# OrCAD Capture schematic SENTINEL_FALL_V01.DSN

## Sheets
1 PG1_BLOCK_DIAGRAM: title: SENTINEL_FALL; rev: V01; note: V01
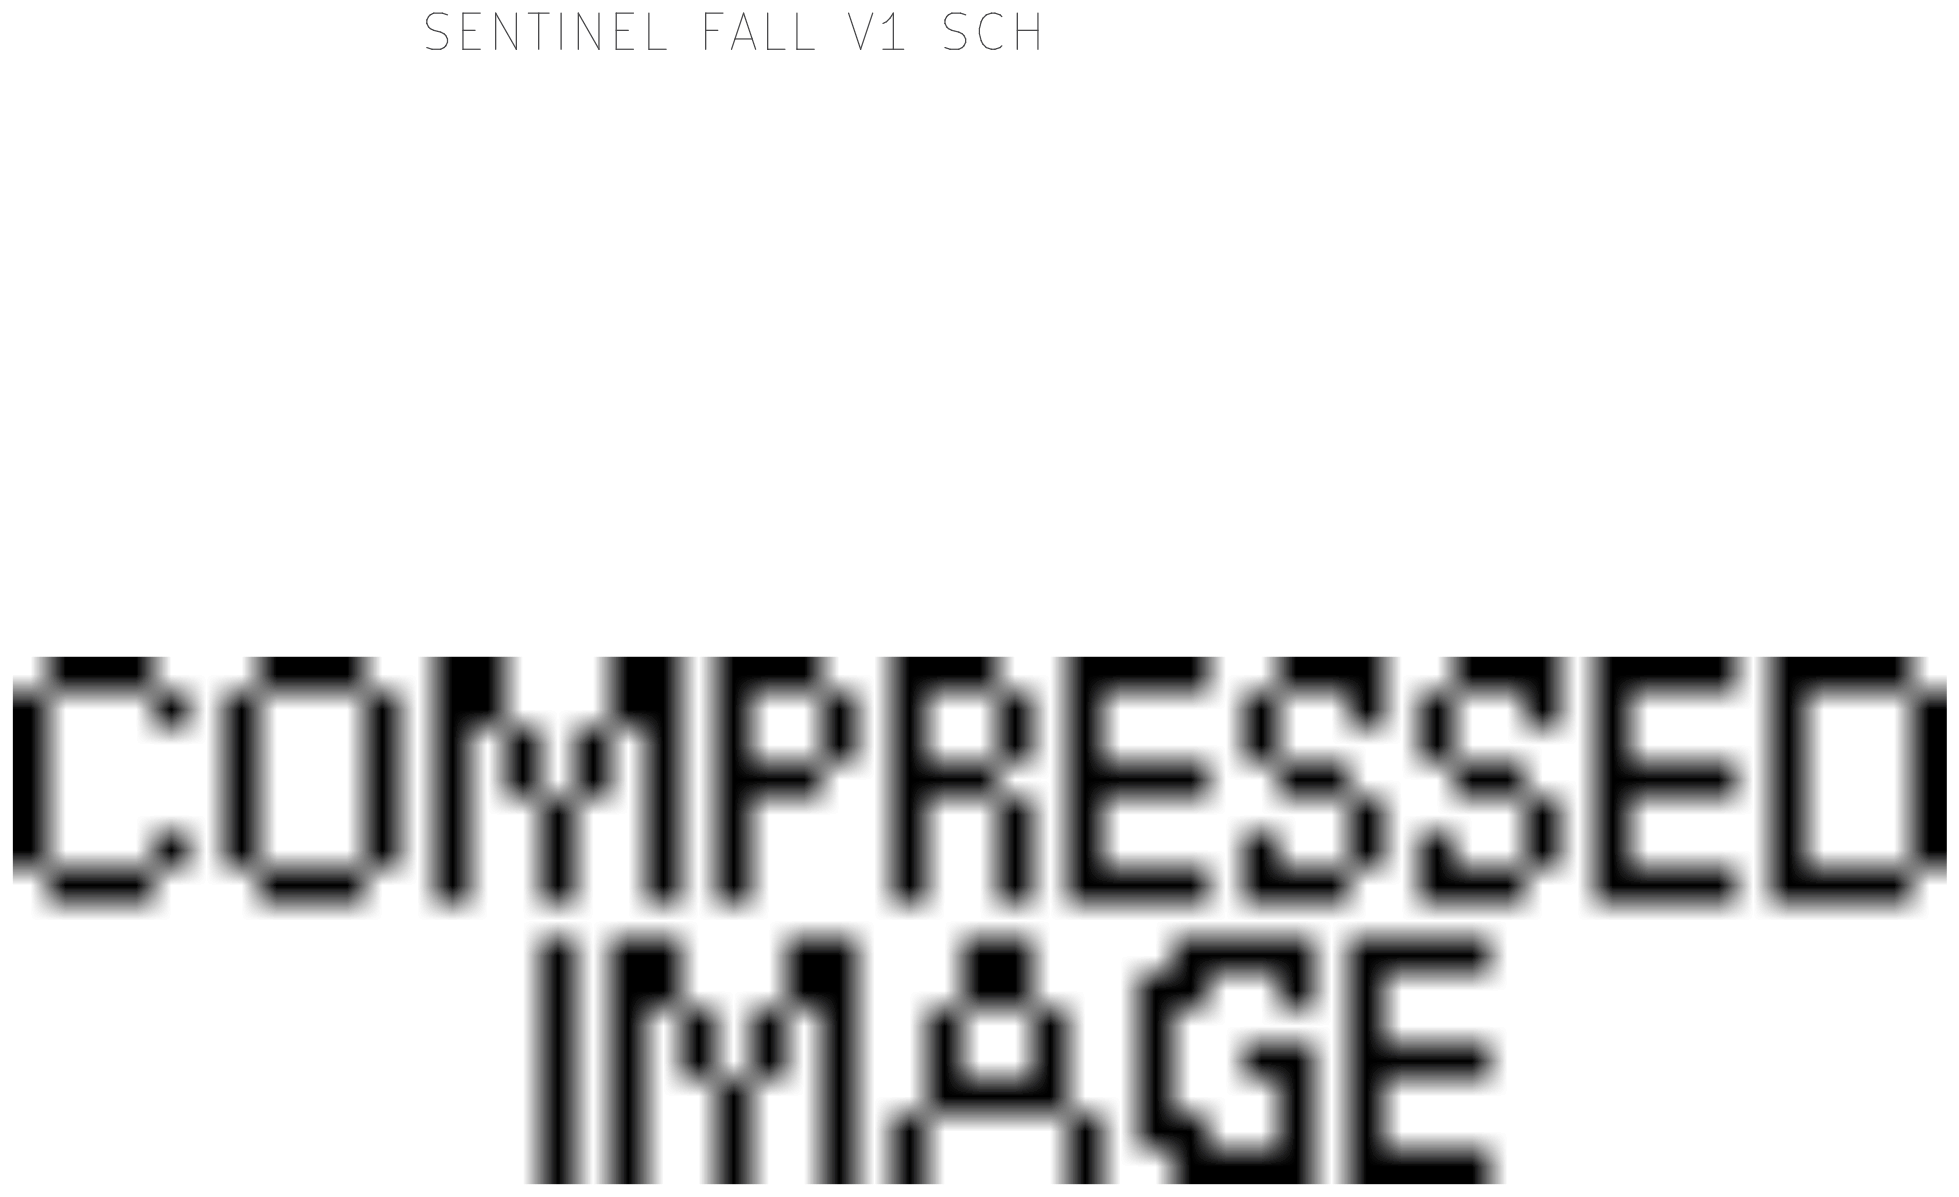
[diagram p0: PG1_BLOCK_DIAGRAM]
2 PG2_BATTERY_CHARGER: size A3
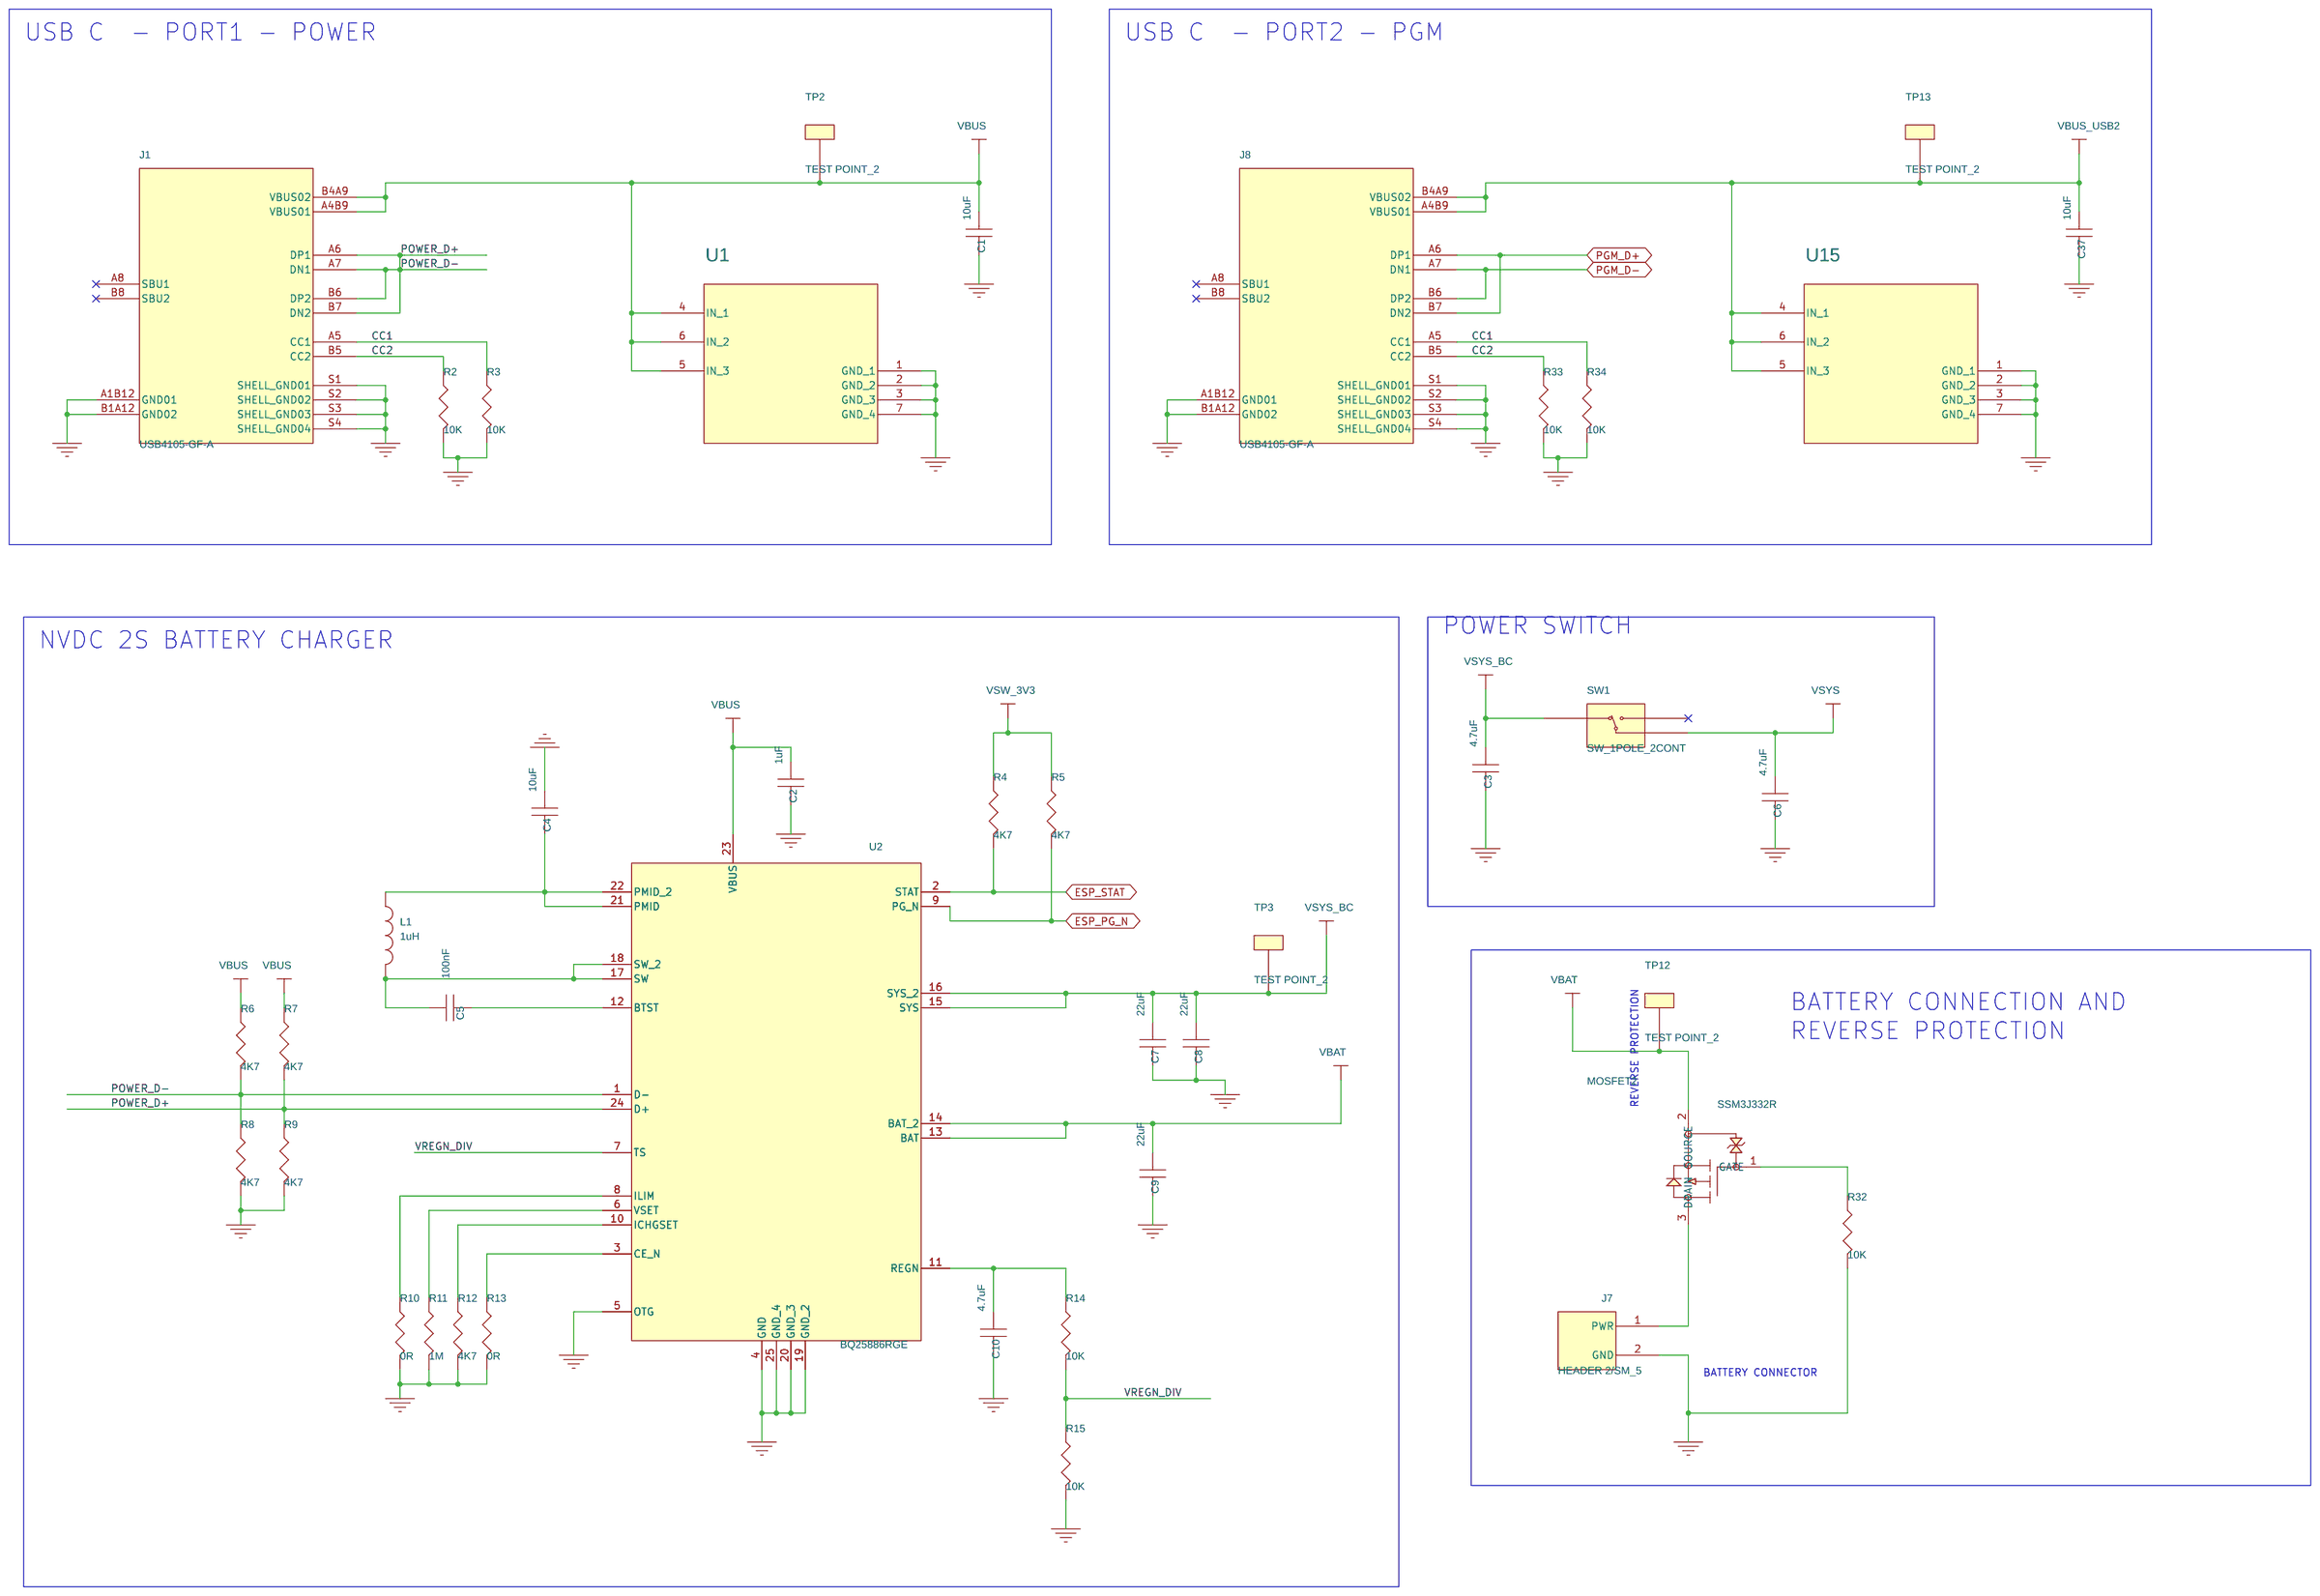
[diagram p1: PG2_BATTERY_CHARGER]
3 PG3_POWER_REG: size A4
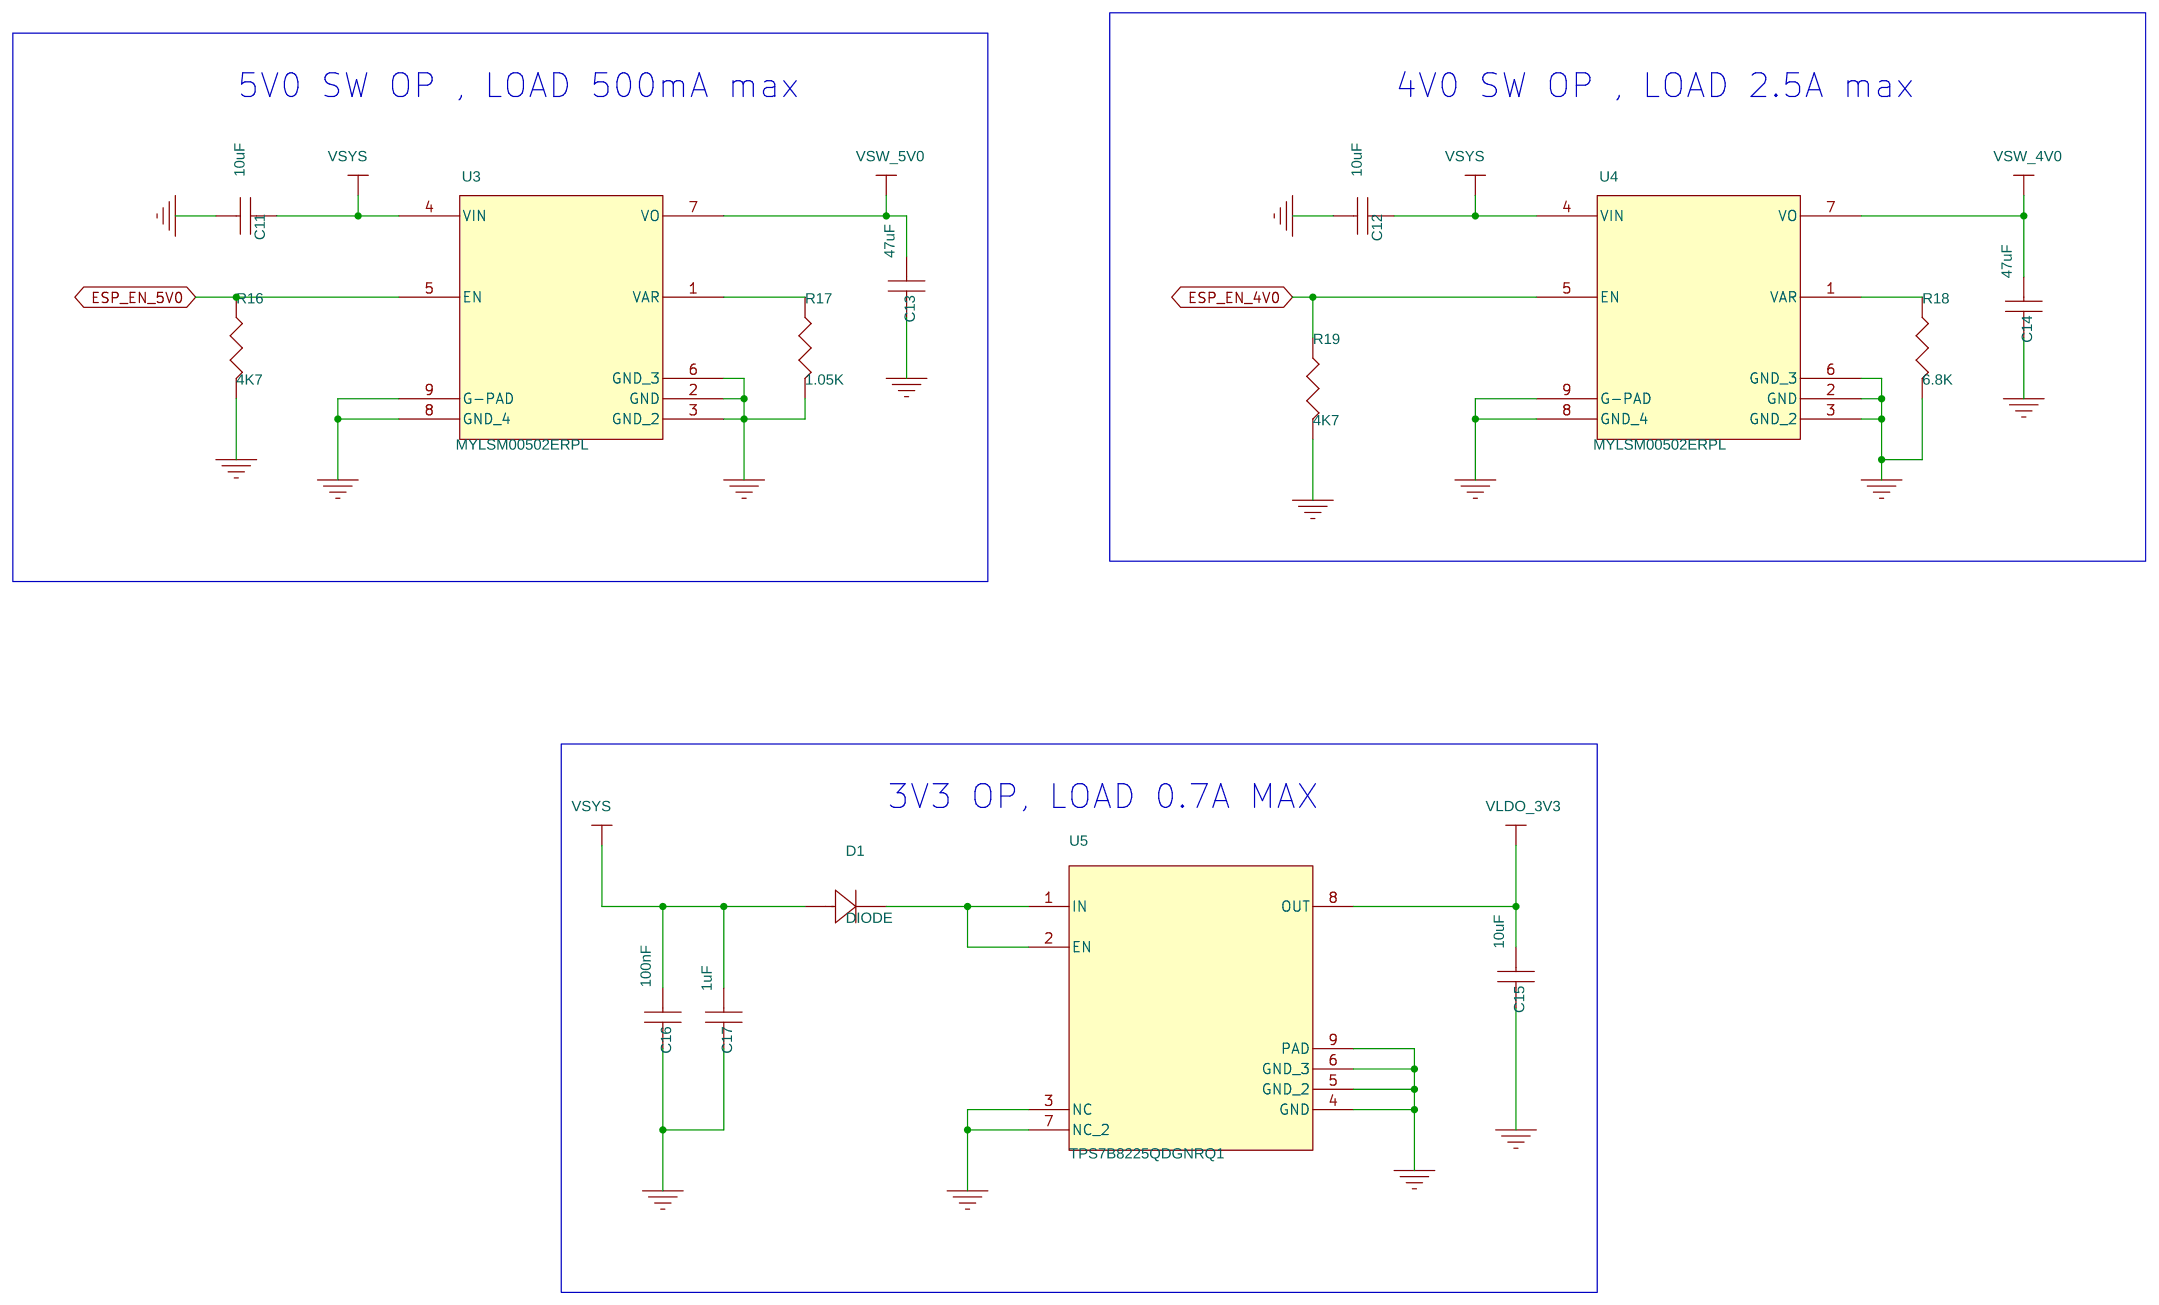
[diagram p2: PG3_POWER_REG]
4 PG4_ESP32: size A3
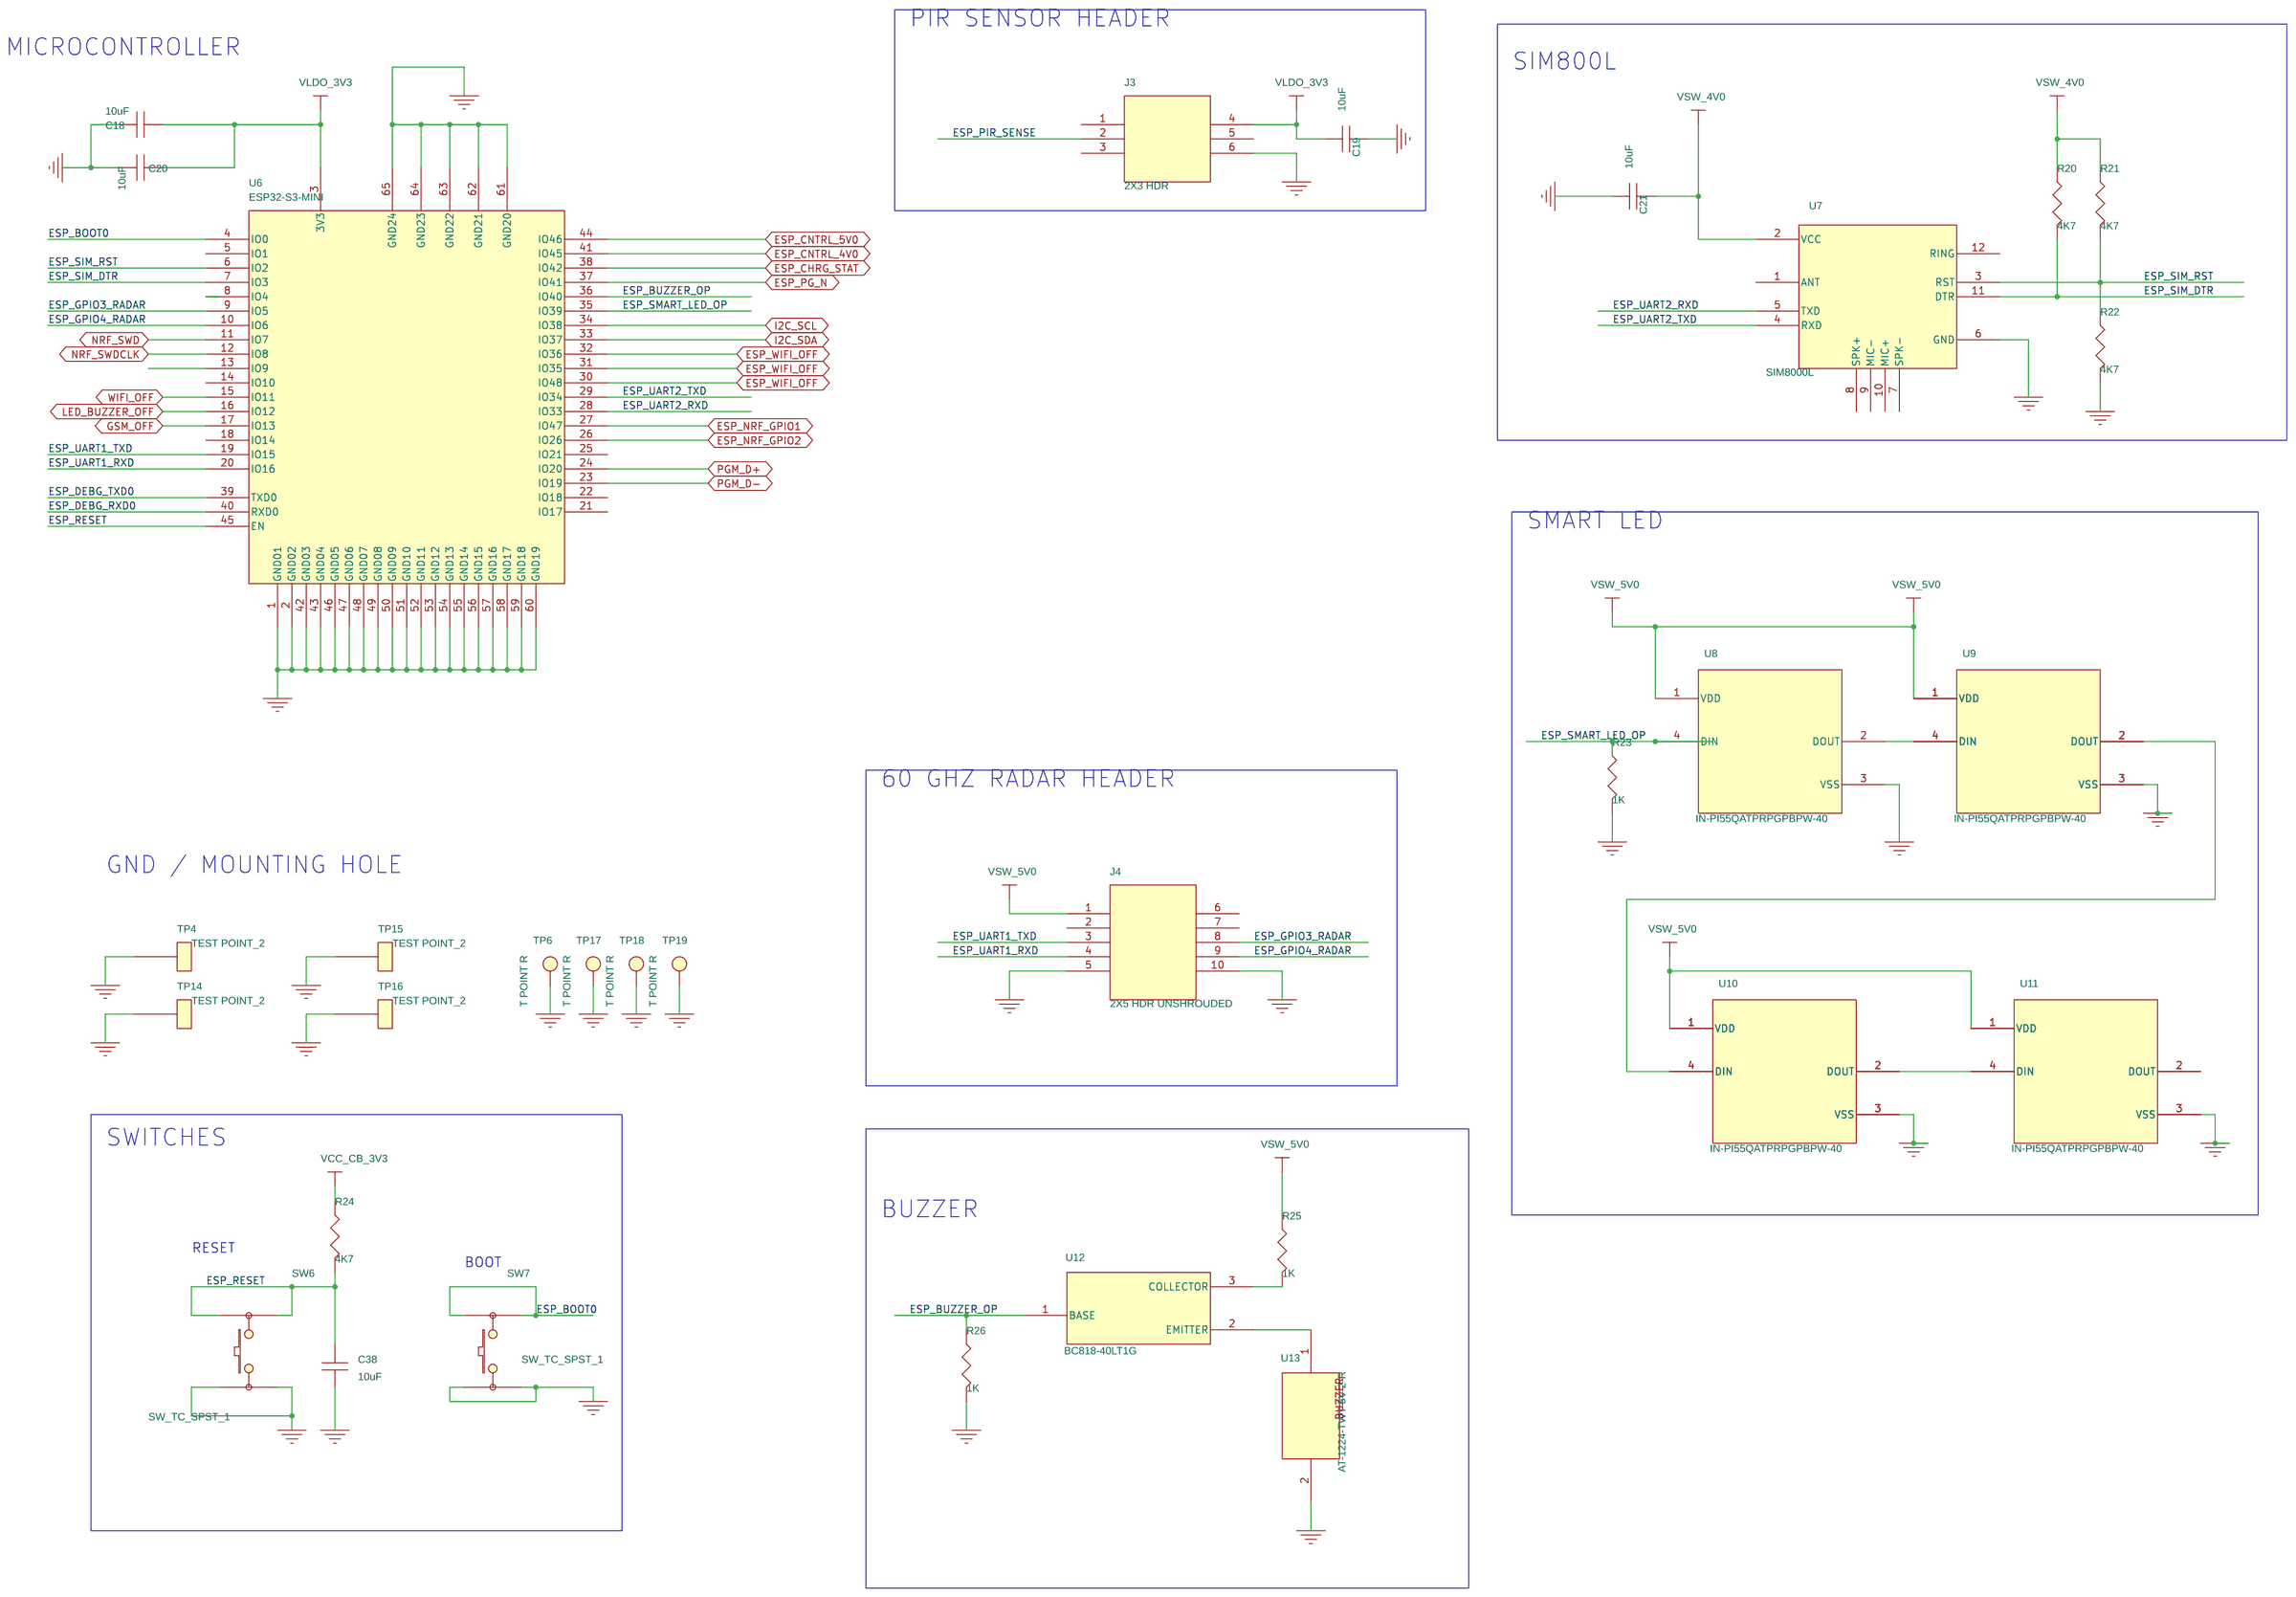
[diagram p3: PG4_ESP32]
5 PG5_NRF_SOC: size A3
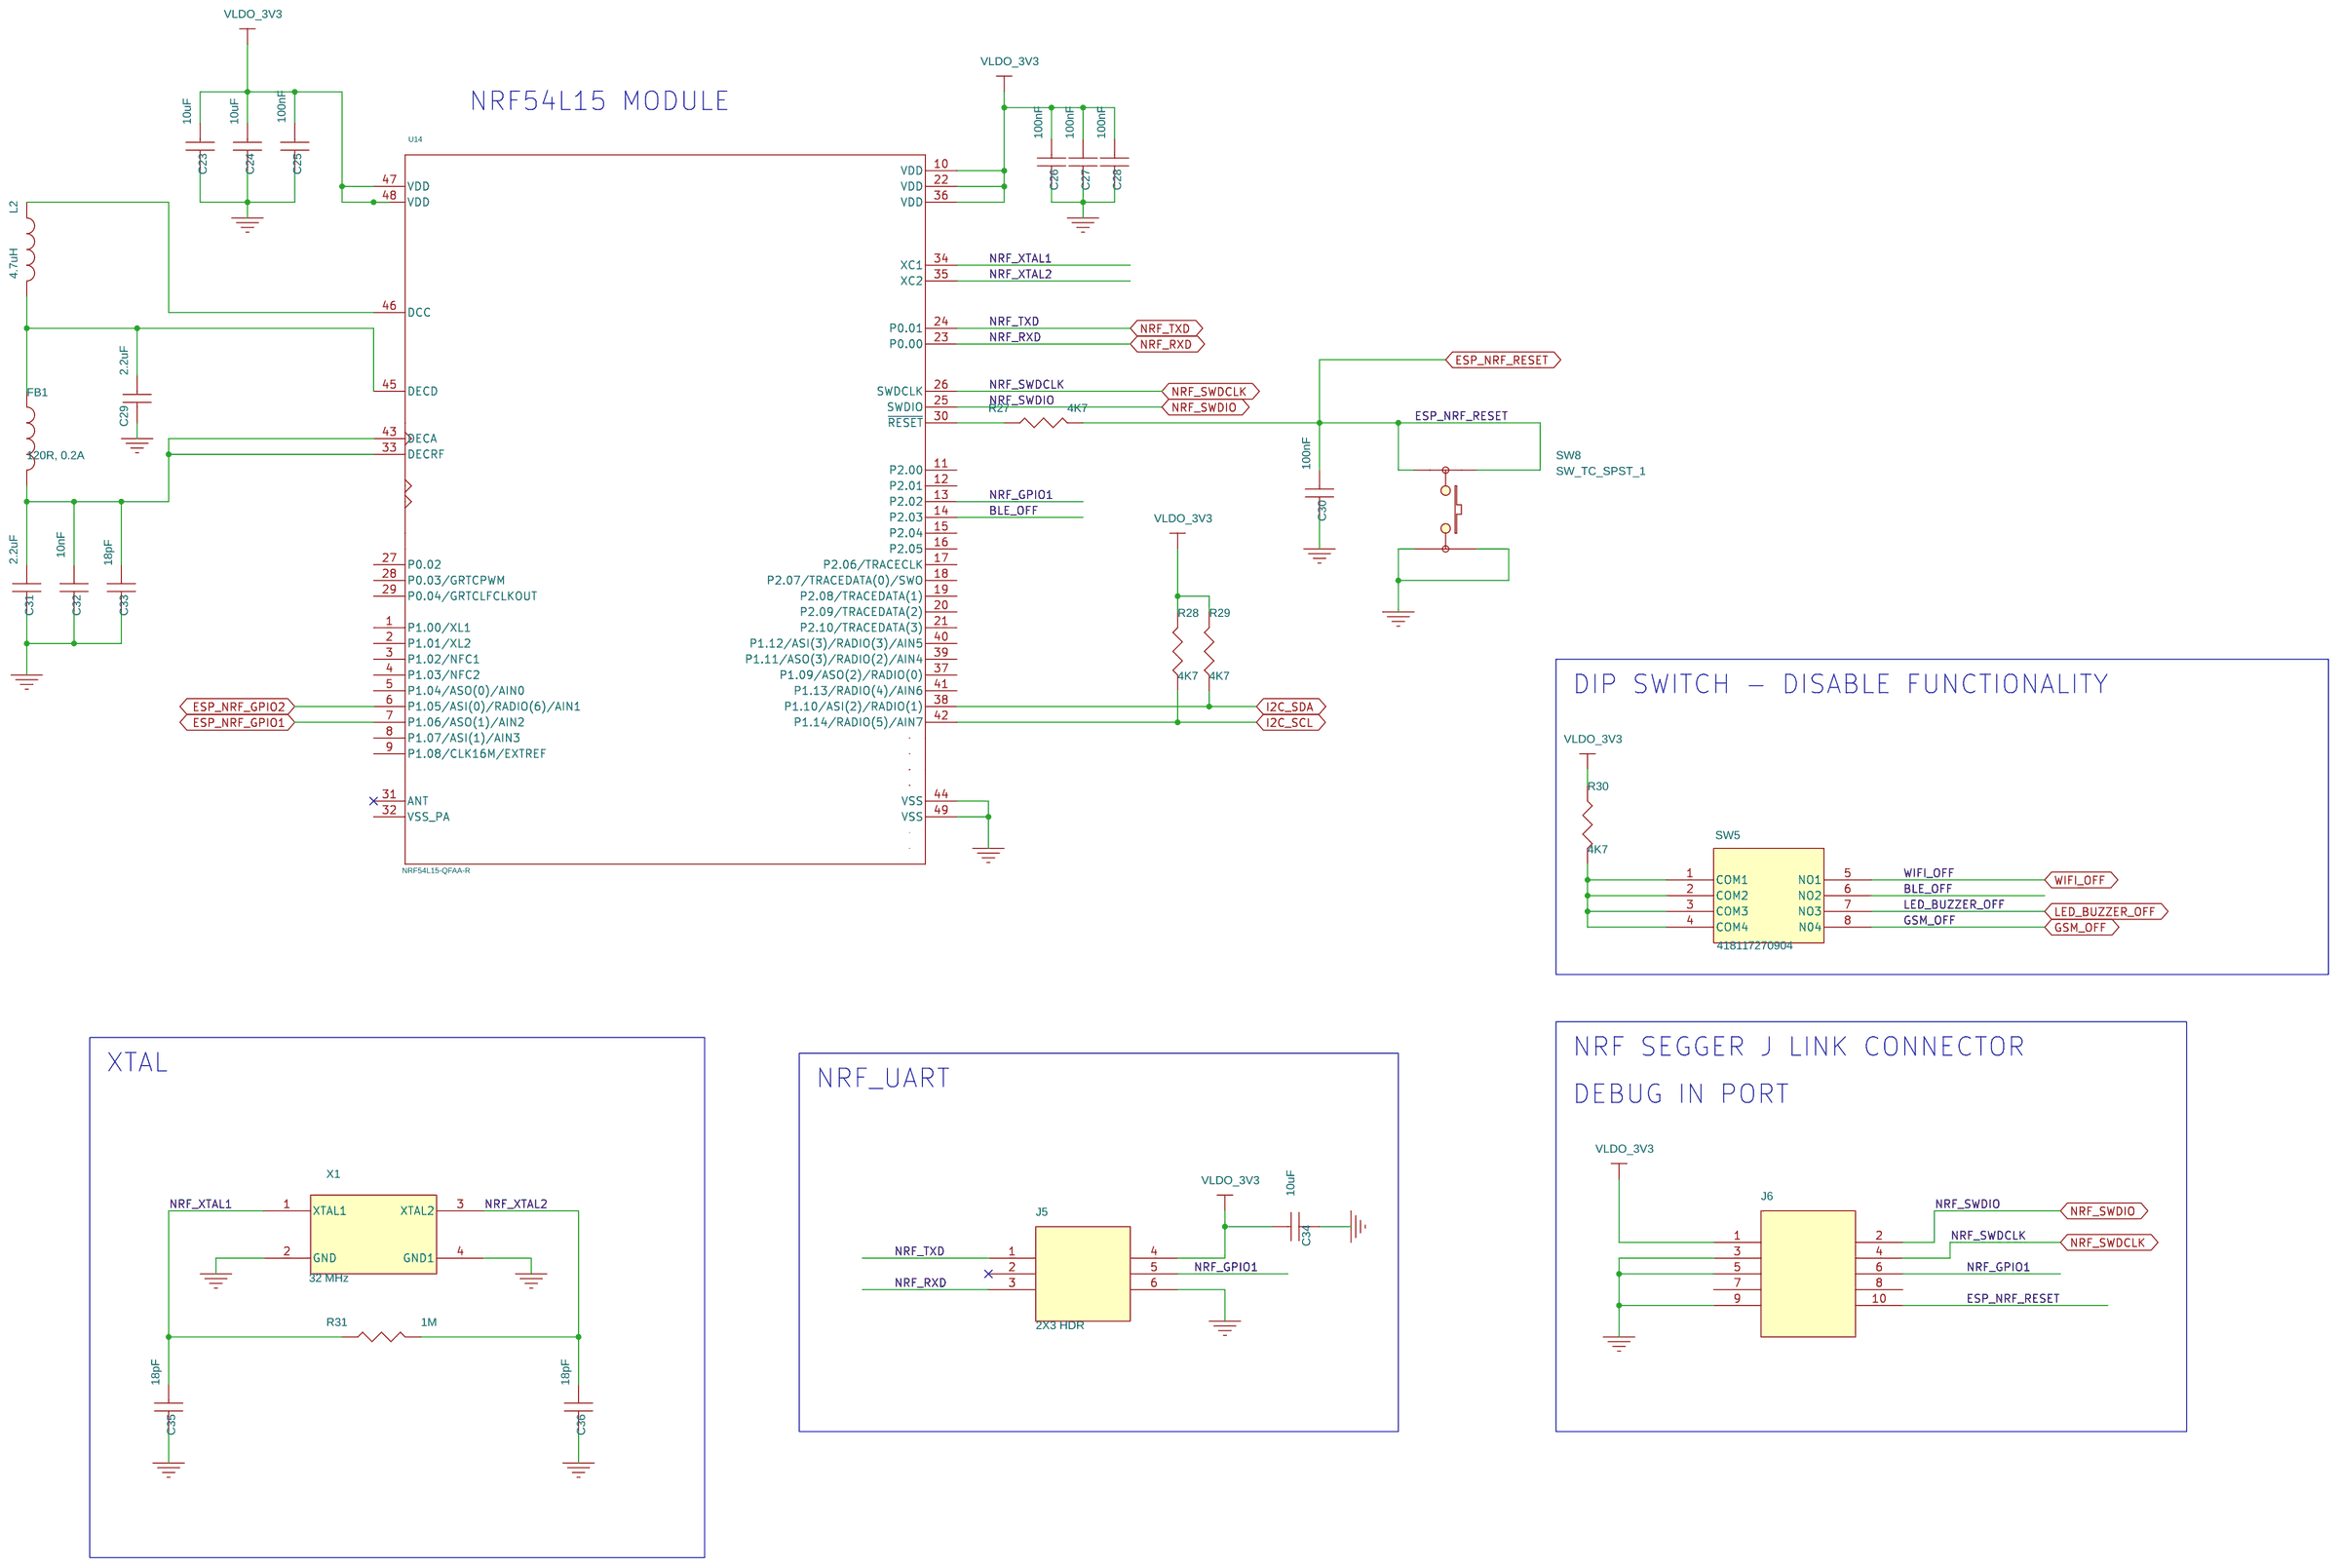
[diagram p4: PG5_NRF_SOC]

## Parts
sheet PG2_BATTERY_CHARGER
C1  10uF  [C0805]
C2  1uF  [C0402]
C3  4.7uF  [C0402]
C4  10uF  [C0402]
C5  100nF  [C0402]
C6  4.7uF  [C0402]
C7  22uF  [C1206]
C8  22uF  [C1206]
C9  22uF  [C1206]
C10  4.7uF  [C0402]
C37  10uF  [C0805]
J1  USB4105-GF-A  [TBD]
J7  HEADER 2/SM_5  [TBD]
J8  USB4105-GF-A  [TBD]
L1  1uH  [L0806]
MOSFET2  SSM3J332R  [SOT-23F_TOS]
R2  10K  [R0402]
R3  10K  [R0402]
R4  4K7  [R0402]
R5  4K7  [R0402]
R6  4K7  [R0402]
R7  4K7  [R0402]
R8  4K7  [R0402]
R9  4K7  [R0402]
R10  0R  [R0402]
R11  1M  [R0402]
R12  4K7  [R0402]
R13  0R  [R0402]
R14  10K  [R0402]
R15  10K  [R0402]
R32  10K  [R0402]
R33  10K  [R0402]
R34  10K  [R0402]
SW1  SW_1POLE_2CONT  [500SSP1_EWI]
TP2  TEST POINT_2  [TBD]
TP3  TEST POINT_2  [TBD]
TP12  TEST POINT_2  [TBD]
TP13  TEST POINT_2  [TBD]
U1  TVS DIODE  [TBD]
U2  BQ25886RGE  [RGE0024H]
U15  TVS DIODE  [TBD]
sheet PG3_POWER_REG
C11  10uF  [C0402]
C12  10uF  [C0402]
C13  47uF  [C1206]
C14  47uF  [C1206]
C15  10uF  [C0402]
C16  100nF  [C0402]
C17  1uF  [C0402]
D1  DIODE  [SMA_DIO]
R16  4K7  [R0402]
R17  1.05K  [R1206]
R18  6.8K  [R0402]
R19  4K7  [R0402]
U3  MYLSM00502ERPL  [MYLSM00502ERPL_MUR]
U4  MYLSM00502ERPL  [MYLSM00502ERPL_MUR]
U5  TPS7B8225QDGNRQ1  [DGN0008D_N]
sheet PG4_ESP32
C18  10uF  [C0402]
C19  10uF  [C0402]
C20  10uF  [C0402]
C21  10uF  [C0402]
C38  10uF  [C0402]
J3  2X3 HDR  [TBD]
J4  2X5 HDR UNSHROUDED  [TBD]
R20  4K7  [R0402]
R21  4K7  [R0402]
R22  4K7  [R0402]
R23  1K  [R1206]
R24  4K7  [R0402]
R25  1K  [R1206]
R26  1K  [R1206]
SW6  SW_TC_SPST_1
SW7  SW_TC_SPST_1
TP4  TEST POINT_2
TP6  T POINT R
TP14  TEST POINT_2
TP15  TEST POINT_2
TP16  TEST POINT_2
TP17  T POINT R
TP18  T POINT R
TP19  T POINT R
U6  ESP32-S3-MINI
U7  SIM8000L  [TBD]
U8  IN-PI55QATPRPGPBPW-40  [TBD]
U9  IN-PI55QATPRPGPBPW-40  [TBD]
U10  IN-PI55QATPRPGPBPW-40  [TBD]
U11  IN-PI55QATPRPGPBPW-40  [TBD]
U12  BC818-40LT1G  [SOT-23-3_1P4X3P040_ONS]
U13  AT-1224-TWT-5V-2-R  [TO_T-12V-2-R_PUI]
sheet PG5_NRF_SOC
C23  10uF  [C0402]
C24  10uF  [C0402]
C25  100nF  [C0402]
C26  100nF  [C0402]
C27  100nF  [C0402]
C28  100nF  [C0402]
C29  2.2uF  [C0402]
C30  100nF  [C0402]
C31  2.2uF  [C0402]
C32  10nF  [C0402]
C33  18pF  [C1206]
C34  10uF  [C0402]
C35  18pF  [C1206]
C36  18pF  [C1206]
FB1  120R, 0.2A  [L0806]
J5  2X3 HDR  [TBD]
J6  2X5 HDR JLINK  [TBD]
L2  4.7uH  [L0603]
R27  4K7  [R0402]
R28  4K7  [R0402]
R29  4K7  [R0402]
R30  4K7  [R0402]
R31  1M  [R0402]
SW5  418117270904  [TBD]
SW8  SW_TC_SPST_1
U14  NRF54L15-QFAA-R  [QFN40P600X600X90-49N]
X1  32 MHz  [TBD]

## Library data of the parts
C1 C37 = CAP_CER_10uF_50V_1206_X7R_10P
C2 C17 = CAP_1UF_25V_1206_10P0
C3 C6 C10 = CAP_CER_4700nF_50V_X7R_1206
C4 C11 C12 C15 C18-C21 C23 C24 C34 C38 = CAP_10UF_50V_X7T_1206
C5 = CAP_100nF_16V_1206_10P0
C7-C9 = 4_CAP__22uF_20%_X5R_0805_35VDC
J1 J8 = CONN_USB_USB4105-GF-A: BOM NOTE: NA
J7 = HEADER_2_SM_5: BOM NOTE: NA; MFG Name: JST Sales America Inc.; MFG Part Number: S2B-PH-SM4-TB
L1 = IND_1uH_11A_1_ukpkg
MOSFET2 = SSM3J332R,LF: BOM NOTE: NA; MFG Name: Toshiba Electronic Devices  Storage Corp.
R2 R3 R14 R15 R32-R34 = RES_10K_1W4_1P0_1206
R4-R9 R12 R16 R19-R22 R24 R27-R30 = RES_4K7_1W4_1P0_1206
R10 R13 = RES_0R0_1W4_1P0_1206
R11 R31 = RES_1M_1W2_0P1_1206
SW1 = 500SSP1S2M2QEA: BOM NOTE: NA; MFG Name: E-Switch
TP2-TP4 TP12-TP16 = TEST_POINT_2: BOM NOTE: NA; MFG Name: NA; MFG Part Number: NA
U1 U15 = IC_TVS_DIODE
U2 = BQ25886RGER: BOM NOTE: NA; MFG Name: Texas Instruments
C13 C14 = CAP_CER_47UF_16V_X5R_1206
C16 C25-C28 C30 = CAP_100nF_50V_1206_X7R
D1 = B260A-13-F: BOM NOTE: NA; MFG Name: Diodes Inc
R17 = RES_1P05K_0W52_0P1_1206
R18 = RES_6P8K_1W4_0P1_1206: BOM NOTE: NA
U3 U4 = MYLSM00502ERPL: BOM NOTE: NA; MFG Name: Murata
U5 = TPS7B8225QDGNRQ1: BOM NOTE: NA; MFG Name: Texas Instruments
J3 J5 = HEADER_6_2X3: BOM NOTE: NA
J4 = HEADER_10_2X5_US: BOM NOTE: NA
R23 R25 R26 = RES_1K_1W4_1P0_1206
SW6-SW8 = SW_TC_SPST_1: BOM NOTE: NA; MFG Name: C&K; MFG Part Number: KMR221NGLFS
TP6 TP17-TP19 = T_POINT_R: BOM NOTE: NA; MFG Name: NA; MFG Part Number: NA
U6 = ESP32-S3-MINI: BOM NOTE: NA; MFG Name: Espressif Systems; MFG Part Number: ESP32-S3-MINI-1-N8
U7 = SIP_IC_SIM800L: BOM NOTE: NA
U8-U11 = IN-PI55QATPRPGPBPW-40: BOM NOTE: NA; MFG Name: Inolux; MFG Part Number: IN-PI55QATPRPGPBPW-30
U12 = NPN_TRANSISTOR_BC818-40LT1G: BOM NOTE: NA; MFG Name: onsemi
U13 = BUZZER_AT-1224-TWT-5V-2-R: BOM NOTE: NA; MFG Name: PUI Audio, Inc.
C29 C31 = CAP_CER_2.2UF_16V_X7R_1206
C32 = 7_CAP_10nF_±10%_50V
C33 C35 C36 = CAP_18PF_125V_1206
FB1 = FB_120R_200mA_0805
J6 = HEADER_10_2X5_SHROUDED: BOM NOTE: NA
L2 = IND_4.7UH_350MA_500MOHM_SM
SW5 = SWITH_DIP: BOM NOTE: NA
U14 = NRF54L15-QFAA-R: BOM NOTE: NA; MFG Name: Nordic Semiconductors
X1 = XTAL_32MHZ: BOM NOTE: NA; MFG Part Number: MP06003

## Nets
GND: C1.2 C2.2 C3.2 C4.1 C6.2 C7.2 C8.2 C9.2 C10.2 C11.1 C12.1 C13.2 C14.2 C15.2 C16.2 C17.2 C18.1 C19.2 C20.1 C21.1 C23.2 C24.2 C25.2 C26.2 C27.2 C28.2 C29.2 C30.2 C31.2 C32.2 C33.2 C34.2 C35.2 C36.2 C37.2 C38.1 J1.A1B12(GND01) J1.B1A12(GND02) J1.S1(SHELL_GND01) J1.S2(SHELL_GND02) J1.S3(SHELL_GND03) J1.S4(SHELL_GND04) J3.6 J4.5 J4.10 J5.6 J6.3 J6.5 J6.9 J7.2(GND) J8.A1B12(GND01) J8.B1A12(GND02) J8.S1(SHELL_GND01) J8.S2(SHELL_GND02) J8.S3(SHELL_GND03) J8.S4(SHELL_GND04) R2.2 R3.2 R8.2 R9.2 R10.2 R11.2 R12.2 R13.2 R15.2 R16.2 R17.2 R18.2 R19.2 R22.2 R23.2 R26.2 R32.2 R33.2 R34.2 SW6.2 SW6.3 SW7.1 SW7.4 SW8.2 SW8.3 TP4.1 TP6.1(TP) TP14.1 TP15.1 TP16.1 TP17.1(TP) TP18.1(TP) TP19.1(TP) U1.1(GND) U1.2(GND) U1.3(GND) U1.7(GND_4) U2.4(GND) U2.5(OTG) U2.19(GND_2) U2.20(GND_3) U2.25(GND_4) U3.2(GND) U3.3(GND_2) U3.6(GND_3) U3.8(GND_4) U3.9(G-PAD) U4.2(GND) U4.3(GND_2) U4.6(GND_3) U4.8(GND_4) U4.9(G-PAD) U5.3(NC) U5.4(GND) U5.5(GND_2) U5.6(GND_3) U5.7(NC_2) U5.9(PAD) U6.1(GND01) U6.2(GND02) U6.42(GND03) U6.43(GND04) U6.46(GND05) U6.47(GND06) U6.48(GND07) U6.49(GND08) U6.50(GND09) U6.51(GND10) U6.52(GND11) U6.53(GND12) U6.54(GND13) U6.55(GND14) U6.56(GND15) U6.57(GND16) U6.58(GND17) U6.59(GND18) U6.60(GND19) U6.61(GND20) U6.62(GND21) U6.63(GND22) U6.64(GND23) U6.65(GND24) U7.6(GND) U8.3(VSS) U9.3(VSS) U10.3(VSS) U11.3(VSS) U13.2 U14.44(VSS) U14.49(VSS) U15.1(GND) U15.2(GND) U15.3(GND) U15.7(GND_4) X1.2(GND) X1.4(GND1)
VBAT: C9.1 MOSFET2.2(SOURCE) TP12.1 U2.13(BAT) U2.14(BAT_2)
VBUS: C1.1 C2.1 J1.A4B9(VBUS01) J1.B4A9(VBUS02) R6.1 R7.1 TP2.1 U1.4(IN_1) U1.5(IN_3) U1.6(IN_2) U2.23(VBUS)
VBUS_USB2: C37.1 J8.A4B9(VBUS01) J8.B4A9(VBUS02) TP13.1 U15.4(IN_1) U15.5(IN_3) U15.6(IN_2)
VCC_CB_3V3: R24.1
VSS_PA: U14.32(VSS_PA)
BLE_OFF: SW5.6(NO2) U14.14(P2.03)
CC1: J1.A5(CC1) J8.A5(CC1) R3.1 R34.1
CC2: J1.B5(CC2) J8.B5(CC2) R2.1 R33.1
ESP_BOOT0: SW7.2 SW7.3 U6.4(IO0)
ESP_BUZZER_OP: R26.1 U6.36(IO40) U12.1(BASE)
ESP_CHRG_STAT: U6.38(IO42)
ESP_CNTRL_4V0: U6.41(IO45)
ESP_CNTRL_5V0: U6.44(IO46)
ESP_DEBG_RXD0: U6.40(RXD0)
ESP_DEBG_TXD0: U6.39(TXD0)
ESP_EN_4V0: R19.1 U4.5(EN)
ESP_EN_5V0: R16.1 U3.5(EN)
ESP_GPIO3_RADAR: J4.8 U6.9(IO5)
ESP_GPIO4_RADAR: J4.9 U6.10(IO6)
ESP_NRF_GPIO1: U6.27(IO47) U14.7(P1.06/ASO(1)/AIN2)
ESP_NRF_GPIO2: U6.26(IO26) U14.6(P1.05/ASI(0)/RADIO(6)/AIN1)
ESP_NRF_RESET: C30.1 J6.10 R27.2 SW8.1 SW8.4
ESP_PG_N: R5.2 U2.9(PG_N) U6.37(IO41)
ESP_PIR_SENSE: J3.2
ESP_RESET: C38.2 R24.2 SW6.1 SW6.4 U6.45(EN)
ESP_SIM_DTR: R20.2 U6.7(IO3) U7.11(DTR)
ESP_SIM_RST: R21.2 R22.1 U6.6(IO2) U7.3(RST)
ESP_SMART_LED_OP: R23.1 U6.35(IO39) U8.4(DIN)
ESP_STAT: R4.2 U2.2(STAT)
ESP_UART1_RXD: J4.4 U6.20(IO16)
ESP_UART1_TXD: J4.3 U6.19(IO15)
ESP_UART2_RXD: U6.28(IO33) U7.5(TXD)
ESP_UART2_TXD: U6.29(IO34) U7.4(RXD)
ESP_WIFI_OFF: U6.30(IO48) U6.31(IO35) U6.32(IO36)
GSM_OFF: SW5.8(N04) U6.17(IO13)
I2C_SCL: R28.1 U6.34(IO38) U14.42(P1.14/RADIO(5)/AIN7)
I2C_SDA: R29.1 U6.33(IO37) U14.38(P1.10/ASI(2)/RADIO(1))
LED_BUZZER_OFF: SW5.7(NO3) U6.16(IO12)
NRF_GPIO1: J5.5 J6.6 U14.13(P2.02)
NRF_RXD: J5.3 U14.23(P0.00)
NRF_SWD: U6.11(IO7)
NRF_SWDCLK: J6.4 U6.12(IO8) U14.26(SWDCLK)
NRF_SWDIO: J6.2 U14.25(SWDIO)
NRF_TXD: J5.1 U14.24(P0.01)
NRF_XTAL1: C35.1 R31.1 U14.34(XC1) X1.1(XTAL1)
NRF_XTAL2: C36.1 R31.2 U14.35(XC2) X1.3(XTAL2)
PGM_D+: J8.A6(DP1) J8.B7(DN2) U6.24(IO20)
PGM_D-: J8.A7(DN1) J8.B6(DP2) U6.23(IO19)
POWER_D+: J1.A6(DP1) J1.B7(DN2) R7.2 R9.1 U2.24(D+)
POWER_D-: J1.A7(DN1) J1.B6(DP2) R6.2 R8.1 U2.1(D-)
VLDO_3V3: C15.1 C18.2 C19.1 C20.2 C23.1 C24.1 C25.1 C26.1 C27.1 C28.1 C34.1 J3.4 J5.4 J6.1 R28.2 R29.2 R30.1 U5.8(OUT) U6.3(3V3) U14.10(VDD) U14.22(VDD) U14.36(VDD) U14.47(VDD) U14.48(VDD)
VREGN_DIV: R14.2 R15.1 U2.7(TS)
VSW_3V3: R4.1 R5.1
VSW_4V0: C14.1 C21.2 R20.1 R21.1 U4.7(VO) U7.2(VCC)
VSW_5V0: C13.1 J4.1 R25.1 U3.7(VO) U8.1(VDD) U9.1(VDD) U10.1(VDD) U11.1(VDD)
VSYS: C6.1 C11.2 C12.2 C16.1 C17.1 D1.2 SW1.2 U3.4(VIN) U4.4(VIN)
VSYS_BC: C3.1 C7.1 C8.1 SW1.1 TP3.1 U2.15(SYS) U2.16(SYS_2)
WIFI_OFF: SW5.5(NO1) U6.15(IO11)
N489525: C4.2 L1.1 U2.21(PMID) U2.22(PMID_2)
N489966: C5.1 L1.2 U2.17(SW) U2.18(SW_2)
N490283: C5.2 U2.12(BTST)
N491328: R10.1 U2.8(ILIM)
N491337: R11.1 U2.6(VSET)
N491346: R12.1 U2.10(ICHGSET)
N491858: C10.1 R14.1 U2.11(REGN)
N492759: R13.1 U2.3(CE_N)
N503956: D1.1 U5.1(IN) U5.2(EN)
N505816: R18.1 U4.1(VAR)
N505904: R17.1 U3.1(VAR)
N532249: U12.2(EMITTER) U13.1
N532253: R25.2 U12.3(COLLECTOR)
N533307: U8.2(DOUT) U9.4(DIN)
N533315: U9.2(DOUT) U10.4(DIN)
N536197: U10.2(DOUT) U11.4(DIN)
N548982: L2.1 U14.46(DCC)
N549115: C29.1 FB1.1 L2.2 U14.45(DECD)
N549518: C31.1 C32.1 C33.1 FB1.2 U14.33(DECRF) U14.43(DECA)
N550099: R27.1 U14.30(~{RESET})
N570476: R30.2 SW5.1(COM1) SW5.2(COM2) SW5.3(COM3) SW5.4(COM4)
N633379: MOSFET2.1(GATE) R32.1
N633403: J7.1(PWR) MOSFET2.3(DRAIN)

Not connected (* = marked no-connect by the designer): J1 A8(SBU1)* B8(SBU2)*; J3 1 3 5; J4 2 6 7; J5 2*; J6 7 8; J8 A8(SBU1)* B8(SBU2)*; SW1 3*; U6 5(IO1) 8(IO4) 13(IO9) 14(IO10) 18(IO14) 21(IO17) 22(IO18) 25(IO21); U7 1(ANT) 7(SPK-) 8(SPK+) 9(MIC-) 10(MIC+) 12(RING); U11 2(DOUT); U14 1(P1.00/XL1) 2(P1.01/XL2) 3(P1.02/NFC1) 4(P1.03/NFC2) 5(P1.04/ASO(0)/AIN0) 8(P1.07/ASI(1)/AIN3) 9(P1.08/CLK16M/EXTREF) 11(P2.00) 12(P2.01) 15(P2.04) 16(P2.05) 17(P2.06/TRACECLK) 18(P2.07/TRACEDATA(0)/SWO) 19(P2.08/TRACEDATA(1)) 20(P2.09/TRACEDATA(2)) 21(P2.10/TRACEDATA(3)) 27(P0.02) 28(P0.03/GRTCPWM) 29(P0.04/GRTCLFCLKOUT) 31(ANT)* 37(P1.09/ASO(2)/RADIO(0)) 39(P1.11/ASO(3)/RADIO(2)/AIN4) 40(P1.12/ASI(3)/RADIO(3)/AIN5) 41(P1.13/RADIO(4)/AIN6)

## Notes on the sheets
sheet 1
- SENTINEL FALL V1 SCH
sheet 2
- USB C  - PORT1 - POWER
- USB C  - PORT2 - PGM
- NVDC 2S BATTERY CHARGER
- POWER SWITCH
- BATTERY CONNECTION AND
- REVERSE PROTECTION
- REVERSE PROTECTION
- BATTERY CONNECTOR
sheet 3
- 5V0 SW OP , LOAD 500mA max
- 4V0 SW OP , LOAD 2.5A max
- 3V3 OP, LOAD 0.7A MAX
sheet 4
- PIR SENSOR HEADER
- MICROCONTROLLER
- SIM800L
- SMART LED
- 60 GHZ RADAR HEADER
- GND / MOUNTING HOLE
- SWITCHES
- BUZZER
- RESET
- BOOT
sheet 5
- NRF54L15 MODULE
- DIP SWITCH - DISABLE FUNCTIONALITY
- NRF SEGGER J LINK CONNECTOR
- XTAL
- NRF_UART
- DEBUG IN PORT
